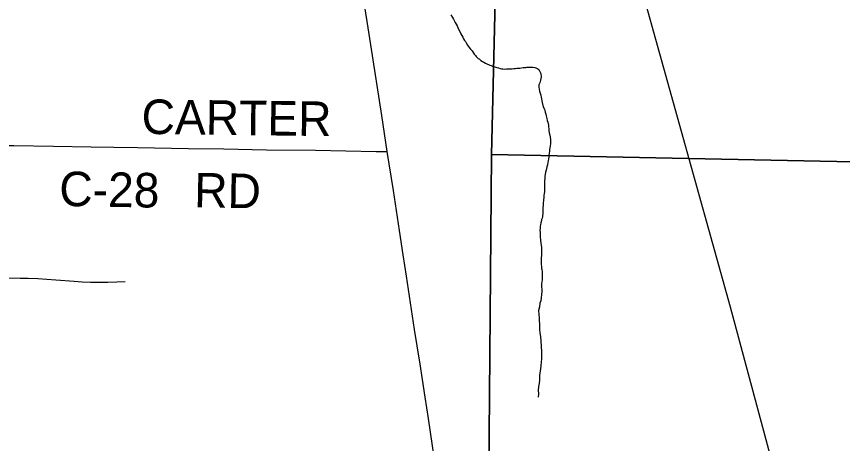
# Model space of a CAD drawing. Extents: x 0 to 34, y 0 to 22.
# Drawn here: x 28.021 to 29.379, y 15.894 to 16.596 of the extents above; entities that cross this region are included whole.
import ezdxf

# ---------------------------------------------------------------- set-up
doc = ezdxf.new("R2010")
doc.units = 0
for name, color, linetype in [('GM_X_County_Road', 7, 'Continuous'), ('GM_X_County_Road_Text', 7, 'Continuous'), ('GM_X_Minor_River', 7, 'Continuous'), ('GM_X_Rail_Line', 7, 'Continuous'), ('GM_X_State_Route', 7, 'Continuous'), ('GM_X_Township_Road', 7, 'Continuous')]:
    doc.layers.add(name, color=color, linetype=linetype)

msp = doc.modelspace()

# ---------------------------------------------------------------- linework, layer by layer
at = {"layer": 'GM_X_County_Road'}
for points in [[(27.9585, 16.3849), (27.9595, 16.3849), (27.9883, 16.3845), (28.0162, 16.3841), (28.0814, 16.383), (28.1435, 16.3821), (28.181, 16.3815)], [(28.181, 16.3815), (28.2197, 16.3809), (28.3035, 16.3795), (28.3619, 16.3785), (28.4321, 16.3774), (28.5123, 16.3766), (28.6122, 16.3746), (28.6301, 16.3743)]]:
    msp.add_lwpolyline(points, dxfattribs=at)
at = {"layer": 'GM_X_Minor_River'}
for points in [[(28.7352, 16.5993), (28.7378, 16.595), (28.7396, 16.5923), (28.7407, 16.5896), (28.7421, 16.5865), (28.7439, 16.5838), (28.7454, 16.5811), (28.7468, 16.5784), (28.7518, 16.568), (28.7532, 16.5653), (28.7547, 16.5626), (28.7561, 16.5599), (28.7579, 16.5572), (28.7594, 16.5552), (28.7605, 16.5529), (28.7627, 16.549), (28.7656, 16.5455), (28.7678, 16.5428), (28.77, 16.5397), (28.7718, 16.537), (28.7736, 16.5343), (28.7755, 16.5323)], [(28.7755, 16.5323), (28.7769, 16.5304), (28.7803, 16.5276), (28.7821, 16.526), (28.7847, 16.5241), (28.787, 16.5225), (28.7896, 16.5213), (28.7922, 16.5197), (28.7956, 16.518), (28.7974, 16.5172), (28.7993, 16.5164), (28.8016, 16.5156), (28.8046, 16.5144), (28.8076, 16.5135), (28.8106, 16.5127), (28.8136, 16.5118), (28.8162, 16.511), (28.8185, 16.5105), (28.8208, 16.5105), (28.8234, 16.51), (28.8265, 16.5103), (28.8291, 16.5102), (28.8329, 16.5101), (28.836, 16.5104), (28.839, 16.5107), (28.8417, 16.511), (28.844, 16.5113), (28.8463, 16.5113), (28.8485, 16.5116), (28.8516, 16.5119), (28.8539, 16.5126), (28.8562, 16.5125), (28.8585, 16.5128), (28.8604, 16.5131), (28.8676, 16.5133), (28.8702, 16.5132), (28.8733, 16.5124), (28.8751, 16.512), (28.8781, 16.5103), (28.88, 16.5095), (28.8814, 16.5061), (28.8832, 16.5026), (28.8838, 16.4973), (28.8834, 16.4946), (28.8829, 16.4916), (28.8816, 16.4871), (28.88, 16.4841), (28.8799, 16.4803), (28.8812, 16.4734), (28.883, 16.4669), (28.884, 16.4638), (28.8853, 16.455), (28.8873, 16.4477), (28.8891, 16.4439), (28.8898, 16.442), (28.8905, 16.4393), (28.8916, 16.4358), (28.8922, 16.4328), (28.8932, 16.4289), (28.8939, 16.4255), (28.8946, 16.4228), (28.8956, 16.4178), (28.8959, 16.4144), (28.8962, 16.4121), (28.8965, 16.4091), (28.8971, 16.4052), (28.8978, 16.4014), (28.8984, 16.3984), (28.8991, 16.3938), (28.8993, 16.3903), (28.8989, 16.3869), (28.8988, 16.3835), (28.8979, 16.3805), (28.8975, 16.3779), (28.8974, 16.3752), (28.8969, 16.3714), (28.8964, 16.3676), (28.8963, 16.365), (28.8959, 16.3623), (28.8954, 16.3593), (28.8949, 16.3566), (28.8941, 16.3525), (28.8932, 16.3491), (28.8924, 16.3464), (28.8919, 16.3438), (28.8911, 16.3404), (28.8897, 16.3332), (28.8896, 16.3298), (28.8895, 16.326), (28.889, 16.3214), (28.8893, 16.3173), (28.8892, 16.3142), (28.8891, 16.3123), (28.8891, 16.3104), (28.889, 16.3081), (28.8885, 16.3055), (28.8884, 16.3021), (28.888, 16.299), (28.8875, 16.2949), (28.8873, 16.2884), (28.8872, 16.2858)], [(28.8872, 16.2858), (28.8867, 16.2827), (28.8866, 16.2785), (28.8865, 16.2747), (28.8864, 16.2721), (28.886, 16.2694), (28.8859, 16.2668), (28.8855, 16.2649), (28.8846, 16.2626), (28.8842, 16.2607), (28.8833, 16.257), (28.8825, 16.2539), (28.8824, 16.2517), (28.882, 16.2498), (28.8819, 16.2479), (28.8818, 16.2452), (28.8821, 16.241), (28.8823, 16.2365), (28.8823, 16.2338), (28.8829, 16.2288), (28.8835, 16.2239), (28.8838, 16.2201), (28.8841, 16.2166), (28.8843, 16.2128), (28.8843, 16.2106), (28.8841, 16.2064), (28.8838, 16.1961), (28.8837, 16.1927), (28.884, 16.1885), (28.8843, 16.1851), (28.8846, 16.182), (28.8849, 16.1801), (28.8852, 16.1771), (28.8855, 16.1744), (28.8854, 16.1714), (28.8855, 16.1634), (28.8842, 16.1566), (28.8841, 16.1531), (28.8844, 16.1512), (28.8847, 16.1478), (28.885, 16.144), (28.8832, 16.1288)], [(27.8709, 16.149), (27.8821, 16.1625), (27.8963, 16.1671), (27.9104, 16.1671), (27.9237, 16.1668), (27.9389, 16.1656), (27.953, 16.1657), (27.9663, 16.1657), (27.9811, 16.1661), (27.9967, 16.1665), (28.0268, 16.1658), (28.0401, 16.1658), (28.0557, 16.1654), (28.0705, 16.1643), (28.0853, 16.1632), (28.1157, 16.1609), (28.1289, 16.1602), (28.1426, 16.1595), (28.1575, 16.1595), (28.1711, 16.1595), (28.1856, 16.1599), (28.1997, 16.1607)], [(28.8832, 16.1288), (28.8816, 16.1247), (28.8808, 16.119), (28.8796, 16.1129), (28.8799, 16.1061), (28.8803, 16.1011), (28.8806, 16.0958), (28.8813, 16.0909), (28.8812, 16.0817), (28.8815, 16.0764), (28.8826, 16.0703), (28.8833, 16.0631), (28.884, 16.0535), (28.8843, 16.0452), (28.8842, 16.0387), (28.8842, 16.0334), (28.8837, 16.0277), (28.8833, 16.0227), (28.8825, 16.0166), (28.8817, 16.0102), (28.8812, 16.0052), (28.8808, 15.9988), (28.8804, 15.993), (28.8795, 15.9877), (28.8791, 15.982), (28.8794, 15.9759), (28.879, 15.9702)]]:
    msp.add_lwpolyline(points, dxfattribs=at)
at = {"layer": 'GM_X_Rail_Line'}
msp.add_lwpolyline([(29.7358, 14.1), (29.6819, 14.2915), (29.4151, 15.3006), (29.1953, 16.1186), (28.963, 16.952), (28.8642, 17.3725), (28.8153, 17.4999), (28.7556, 17.6382), (28.6863, 17.7778), (28.4883, 18.0894), (28.4584, 18.1342), (28.4272, 18.1626), (28.3947, 18.1748), (28.3594, 18.181)], dxfattribs=at)
at = {"layer": 'GM_X_State_Route'}
for points in [[(28.5427, 16.9377), (28.5459, 16.9167), (28.5498, 16.8921), (28.5608, 16.8253), (28.567, 16.7828), (28.5719, 16.7514), (28.576, 16.7238), (28.5819, 16.685), (28.5986, 16.5775), (28.6032, 16.5499), (28.6213, 16.4337), (28.6301, 16.3743)], [(28.6301, 16.3743), (28.6401, 16.3103), (28.6501, 16.2445), (28.6563, 16.2046), (28.6617, 16.1696), (28.675, 16.0817), (28.6791, 16.0546), (28.684, 16.0246), (28.6878, 15.9994), (28.6925, 15.9705), (28.6977, 15.9355), (28.708, 15.8679)]]:
    msp.add_lwpolyline(points, dxfattribs=at)
at = {"layer": 'GM_X_Township_Road'}
for points in [[(28.7934, 15.3155), (28.8021, 16.3696), (28.8142, 16.8756), (28.8168, 16.9882), (28.8261, 17.3752)], [(28.8261, 17.3752), (28.8168, 16.9882), (28.8142, 16.8756), (28.8021, 16.3696), (29.7483, 16.3505)]]:
    msp.add_lwpolyline(points, dxfattribs=at)
msp.add_lwpolyline([(28.7673, 14.1), (30.3167, 14.1), (30.3167, 16.335), (30.315, 16.335), (30.2735, 16.3357), (30.2681, 16.3359), (30.2361, 16.3375), (29.7483, 16.3505), (28.8021, 16.3696), (28.7934, 15.3155), (28.7709, 14.3107)], close=True, dxfattribs=at)

# ---------------------------------------------------------------- texts
at = {"layer": 'GM_X_County_Road_Text'}
for s, rotation, p in [('CARTER', 359.3031, (28.2262, 16.4034)), ('C-28', 358.977, (28.0907, 16.2849)), ('RD', 359.0109, (28.3126, 16.2826))]:
    msp.add_text(s, height=0.05682, rotation=rotation, dxfattribs=at).set_placement(p)

doc.saveas('drawing.dxf')
